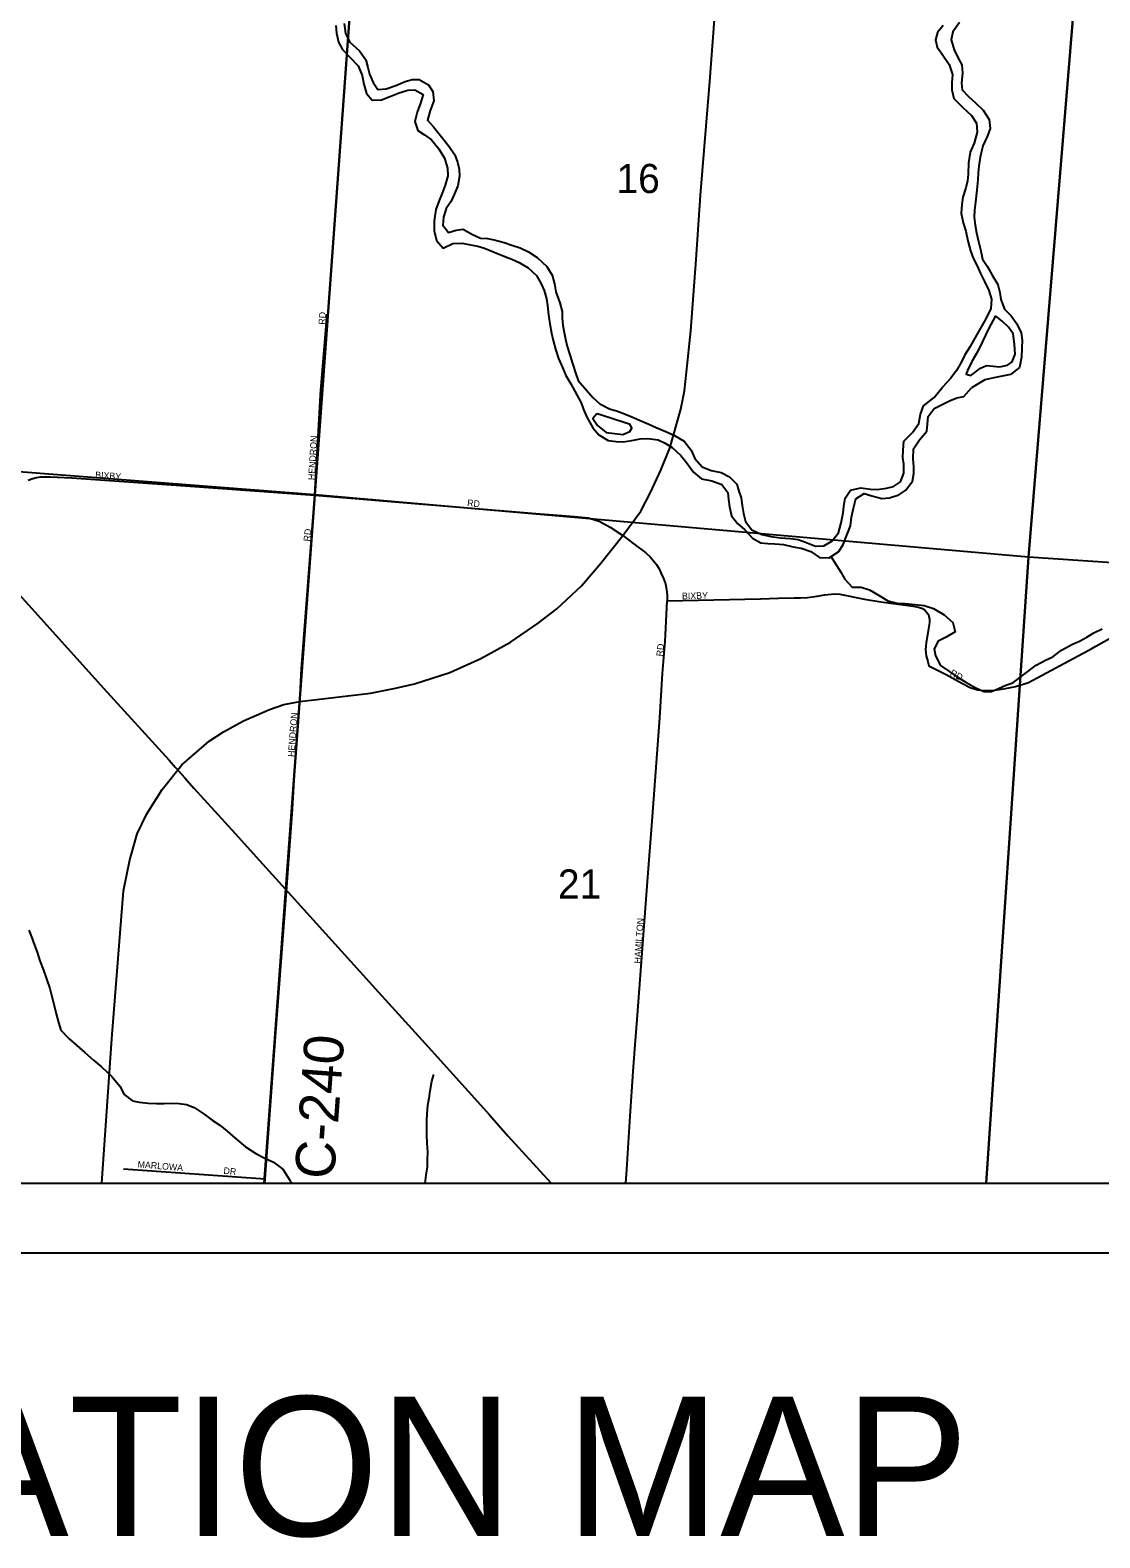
# Model space of a CAD drawing. Extents: x 0 to 34, y 0 to 22.
# Drawn here: x 5.595 to 7.131, y 13.591 to 15.756 of the extents above; entities that cross this region are included whole.
import ezdxf

# ---------------------------------------------------------------- set-up
doc = ezdxf.new("R2010")
doc.units = 0
for name, color, linetype in [('GM_X_City_Street', 7, 'Continuous'), ('GM_X_City_Street_Text', 7, 'Continuous'), ('GM_X_County_Road', 7, 'Continuous'), ('GM_X_County_Road_Text', 7, 'Continuous'), ('GM_X_Minor_River', 7, 'Continuous'), ('GM_X_Rail_Line', 7, 'Continuous'), ('GM_X_Section', 7, 'Continuous'), ('GM_X_Section_Text', 7, 'Continuous'), ('GM_X_State_Route', 7, 'Continuous'), ('GM_X_Township', 7, 'Continuous'), ('GM_X_Township_Road', 7, 'Continuous'), ('GM_X_Township_Subdivision', 7, 'Continuous'), ('GM_X_Township_Subdivision_Text', 7, 'Continuous'), ('SH_Data', 7, 'Continuous')]:
    doc.layers.add(name, color=color, linetype=linetype)

msp = doc.modelspace()

# ---------------------------------------------------------------- linework, layer by layer
at = {"layer": 'GM_X_City_Street'}
for points in [[(6.0119, 15.2328), (6.0214, 15.3483)], [(6.0039, 15.0882), (6.0118, 15.2315), (6.0119, 15.2328)], [(5.5921, 15.1097), (5.5987, 15.112), (5.604, 15.1135), (5.6097, 15.1143), (5.6158, 15.1146), (5.6238, 15.1146), (5.6549, 15.1131), (5.818, 15.1016), (6.0039, 15.0882), (6.3211, 15.062), (6.3526, 15.0594), (6.377, 15.0576), (6.3818, 15.0571)], [(5.9741, 14.6791), (5.9747, 14.6891), (5.9821, 14.7921), (5.9848, 14.8387), (6.0039, 15.0882)], [(6.3818, 15.0571), (6.3966, 15.0555), (6.4047, 15.0533), (6.4121, 15.0509), (6.4282, 15.0422), (6.4465, 15.03), (6.4626, 15.018), (6.4793, 15.0055), (6.486, 14.9992), (6.4904, 14.9938), (6.4947, 14.9884), (6.4983, 14.9825), (6.5011, 14.9765), (6.5049, 14.9683), (6.5075, 14.9606), (6.509, 14.9527), (6.5098, 14.9445), (6.5101, 14.9364)], [(7.1255, 14.8711), (7.154, 14.887), (7.1931, 14.9094), (7.2643, 14.9712), (7.2708, 14.9757), (7.2754, 14.9782), (7.2819, 14.9817), (7.2893, 14.9851), (7.2981, 14.9851)], [(6.5101, 14.9364), (6.6441, 14.9394), (6.6698, 14.9402), (6.6925, 14.9407), (6.6996, 14.9406)], [(6.6996, 14.9406), (6.7014, 14.9406), (6.7117, 14.941), (6.7254, 14.9431), (6.7365, 14.9452), (6.7454, 14.9461), (6.7524, 14.9463), (6.7578, 14.9459), (6.7936, 14.939), (6.8167, 14.9351), (6.8633, 14.929), (6.8684, 14.9279), (6.8723, 14.9269), (6.8767, 14.9253), (6.8804, 14.9227), (6.8831, 14.9198), (6.8852, 14.9168), (6.8859, 14.9142), (6.8867, 14.9102), (6.8867, 14.9055), (6.886, 14.8995), (6.8821, 14.876), (6.8811, 14.8664), (6.8818, 14.8576), (6.8842, 14.8495), (6.886, 14.8431), (6.9106, 14.8305), (6.9342, 14.8179), (6.9453, 14.8121), (6.9555, 14.8087), (6.9657, 14.8075), (6.9807, 14.8082), (6.9961, 14.8105), (7.0101, 14.8133), (7.0277, 14.8187), (7.0288, 14.8193)], [(6.4636, 14.2925), (6.4672, 14.3414), (6.4815, 14.5333), (6.4887, 14.6262), (6.4994, 14.7684), (6.5034, 14.8322), (6.5069, 14.8782), (6.5101, 14.9364)]]:
    msp.add_lwpolyline(points, dxfattribs=at)
at = {"layer": 'GM_X_County_Road'}
for points in [[(5.932, 14.1), (5.9324, 14.1065), (5.9477, 14.3172), (5.9632, 14.5192), (5.9717, 14.6374), (5.9741, 14.6791)], [(6.4505, 14.1), (6.4518, 14.12), (6.457, 14.1964), (6.4613, 14.2604), (6.4636, 14.2925)]]:
    msp.add_lwpolyline(points, dxfattribs=at)
at = {"layer": 'GM_X_Minor_River'}
for points in [[(6.0339, 15.7624), (6.0349, 15.7514), (6.0378, 15.7385), (6.0438, 15.7282), (6.0539, 15.7178), (6.0659, 15.7045), (6.0718, 15.6908), (6.0743, 15.6782), (6.078, 15.6649), (6.0862, 15.6553), (6.0995, 15.6556), (6.1128, 15.6612), (6.1249, 15.6657), (6.1375, 15.6697), (6.1473, 15.6704), (6.1594, 15.6635), (6.1555, 15.651), (6.1508, 15.6381), (6.1477, 15.6249), (6.1517, 15.6119), (6.1615, 15.6058), (6.1716, 15.5985), (6.1821, 15.5855), (6.1903, 15.5722), (6.1943, 15.5577), (6.195, 15.5467), (6.1911, 15.5331)], [(6.046, 15.7653), (6.0481, 15.7513), (6.0541, 15.7387), (6.068, 15.7261), (6.0773, 15.7131), (6.0802, 15.7021), (6.0824, 15.6926), (6.0876, 15.6808), (6.0943, 15.6705), (6.1064, 15.6715), (6.1201, 15.6763), (6.1338, 15.6823), (6.1437, 15.6852), (6.1539, 15.6848), (6.1671, 15.6775), (6.1734, 15.6679), (6.1748, 15.6542), (6.1694, 15.6403), (6.1658, 15.6266), (6.1741, 15.6171), (6.1857, 15.6026), (6.1969, 15.5888), (6.2051, 15.577), (6.2088, 15.5663), (6.211, 15.5561), (6.2116, 15.5462)], [(6.9062, 15.7625), (6.8982, 15.7523), (6.8954, 15.7421), (6.898, 15.7315), (6.9051, 15.7215), (6.9148, 15.7067), (6.9196, 15.6922), (6.9191, 15.6801), (6.919, 15.6702), (6.9215, 15.6577), (6.9346, 15.645), (6.947, 15.6332), (6.9541, 15.6225), (6.9551, 15.6092), (6.9508, 15.5937), (6.945, 15.5808), (6.9426, 15.5653), (6.9424, 15.5493), (6.9416, 15.5395), (6.9388, 15.5293), (6.9349, 15.516), (6.9333, 15.5054), (6.9324, 15.4929), (6.9353, 15.4792), (6.939, 15.4674), (6.9419, 15.4533), (6.9459, 15.4389), (6.9496, 15.4286), (6.9552, 15.4176), (6.96, 15.4065), (6.966, 15.3951), (6.9719, 15.3821), (6.9759, 15.3696), (6.9751, 15.3563), (6.9677, 15.3412), (6.96, 15.328), (6.9523, 15.3144), (6.9454, 15.3015), (6.9377, 15.2895), (6.9327, 15.2796), (6.9254, 15.2672), (6.9173, 15.2562), (6.9054, 15.243)], [(6.9301, 15.7669), (6.9201, 15.7537), (6.9181, 15.7419), (6.9222, 15.7275), (6.9281, 15.7157), (6.9333, 15.7061), (6.9344, 15.6947), (6.9327, 15.68), (6.9337, 15.6701), (6.9427, 15.6605), (6.9529, 15.6517), (6.9641, 15.641), (6.9727, 15.6276), (6.9737, 15.6147), (6.9702, 15.6041), (6.9636, 15.5898), (6.9597, 15.5735), (6.9577, 15.5606), (6.9565, 15.5511), (6.956, 15.5409), (6.9547, 15.5265), (6.9527, 15.509), (6.9514, 15.4973), (6.9509, 15.4874), (6.9523, 15.476), (6.9545, 15.465), (6.9574, 15.4525), (6.9603, 15.4392), (6.9629, 15.427), (6.9696, 15.4171), (6.977, 15.4041), (6.9848, 15.3908), (6.9878, 15.3794), (6.9892, 15.3691), (6.9944, 15.3554), (7.0041, 15.3455), (7.0123, 15.3344), (7.0186, 15.3211), (7.0201, 15.3108), (7.0192, 15.299), (7.0191, 15.2865), (7.0159, 15.2714), (7.0033, 15.2612), (6.9889, 15.2587), (6.979, 15.2565), (6.9661, 15.2536), (6.9473, 15.2421)], [(6.2116, 15.5462), (6.2092, 15.5325), (6.2038, 15.5197), (6.1992, 15.5095), (6.1927, 15.4997), (6.1887, 15.4872), (6.1879, 15.4758), (6.1961, 15.4651), (6.2071, 15.4688), (6.217, 15.4699), (6.2294, 15.4629), (6.2418, 15.4571), (6.2517, 15.4567), (6.2615, 15.4547), (6.2759, 15.4508), (6.2868, 15.4473), (6.2989, 15.4434), (6.3106, 15.4376), (6.323, 15.4295), (6.3369, 15.4165), (6.3447, 15.4039), (6.348, 15.3914), (6.3502, 15.38), (6.3557, 15.3644), (6.359, 15.3518), (6.3593, 15.3424), (6.3603, 15.3321), (6.3621, 15.3218), (6.3639, 15.3123), (6.3665, 15.3017), (6.3705, 15.288), (6.3742, 15.277), (6.3786, 15.2625), (6.3819, 15.253)], [(6.1911, 15.5331), (6.1868, 15.5217), (6.1825, 15.5115), (6.1779, 15.4983), (6.1751, 15.482), (6.1753, 15.4679), (6.1786, 15.4539), (6.1883, 15.4428), (6.202, 15.4495), (6.2153, 15.4498), (6.2277, 15.4474), (6.238, 15.4458), (6.2478, 15.4427), (6.2617, 15.4373), (6.2745, 15.4318), (6.287, 15.4272), (6.2976, 15.4222), (6.3104, 15.4148), (6.3224, 15.4037), (6.3291, 15.3916), (6.3335, 15.382), (6.3364, 15.3702), (6.3379, 15.3604), (6.3396, 15.3471), (6.3414, 15.3342), (6.3439, 15.3209), (6.3461, 15.3102), (6.3494, 15.2977), (6.3538, 15.2843), (6.3597, 15.2714), (6.3642, 15.26), (6.3716, 15.2478)], [(6.9818, 15.3456), (6.9714, 15.3268), (6.9629, 15.309), (6.9555, 15.2939), (6.9478, 15.2799), (6.9413, 15.2674), (6.9393, 15.2621), (6.9461, 15.2602), (6.9602, 15.2707), (6.9686, 15.2744), (6.9784, 15.2732), (6.9875, 15.2724), (6.9989, 15.2749), (7.0057, 15.2794), (7.0096, 15.2904), (7.009, 15.3048), (7.0069, 15.32), (7.0002, 15.3296), (6.9912, 15.338)], [(6.9912, 15.338), (6.9818, 15.3456)], [(6.3716, 15.2478), (6.3862, 15.2208), (6.3899, 15.2112), (6.3947, 15.2002), (6.4031, 15.1849), (6.4117, 15.1749), (6.4252, 15.1667), (6.4369, 15.1651), (6.4468, 15.1645), (6.4593, 15.1666), (6.4714, 15.1691), (6.4824, 15.1697), (6.4971, 15.1676), (6.5069, 15.1629), (6.517, 15.1564), (6.5297, 15.1452), (6.5376, 15.1352), (6.5476, 15.1214), (6.5595, 15.1114), (6.5739, 15.1085), (6.5886, 15.1034), (6.5971, 15.0919), (6.5981, 15.082), (6.5995, 15.0714), (6.6023, 15.0584), (6.6112, 15.0477), (6.6217, 15.0384), (6.6325, 15.0265), (6.6445, 15.0199), (6.6547, 15.0186), (6.6646, 15.0181), (6.677, 15.0172), (6.691, 15.014), (6.7023, 15.0119), (6.7163, 15.0072), (6.729, 14.9986), (6.7426, 14.9981), (6.7564, 15.0074), (6.763, 15.0175), (6.7689, 15.0333), (6.7732, 15.0439), (6.7749, 15.0568), (6.7777, 15.0696), (6.7809, 15.0829), (6.7927, 15.0907), (6.804, 15.0871), (6.8184, 15.0835), (6.8294, 15.0845), (6.8427, 15.0888), (6.853, 15.0951), (6.8622, 15.1083), (6.8643, 15.1193), (6.8644, 15.1287), (6.8635, 15.1405), (6.864, 15.1545), (6.8722, 15.1677), (6.8829, 15.1801), (6.8838, 15.1903), (6.8851, 15.2009), (6.8936, 15.2125), (6.905, 15.2184), (6.9157, 15.2236), (6.926, 15.228), (6.9359, 15.2298), (6.9473, 15.2421)], [(6.3819, 15.253), (6.4034, 15.2285), (6.4131, 15.2193), (6.427, 15.2122), (6.4387, 15.209), (6.4485, 15.2051), (6.459, 15.2008), (6.4737, 15.1945), (6.4835, 15.1902), (6.494, 15.1855), (6.509, 15.1792), (6.5203, 15.1738), (6.5346, 15.1656), (6.5442, 15.1529), (6.5497, 15.1407), (6.5602, 15.1288), (6.5733, 15.1237), (6.5873, 15.1205), (6.5993, 15.1146), (6.6098, 15.1038), (6.613, 15.0939), (6.6163, 15.0844), (6.6177, 15.0734), (6.6194, 15.062), (6.6226, 15.0502), (6.6316, 15.0383), (6.6458, 15.0317), (6.659, 15.0288), (6.6726, 15.0271), (6.687, 15.0261), (6.6983, 15.0245), (6.7085, 15.0209), (6.7228, 15.015), (6.7349, 15.0152), (6.7467, 15.0219), (6.756, 15.0339), (6.76, 15.0483), (6.7628, 15.0626), (6.7637, 15.0721), (6.7658, 15.0838), (6.7731, 15.0955), (6.7883, 15.0987), (6.8019, 15.097), (6.8117, 15.0965), (6.825, 15.0982), (6.8353, 15.1007), (6.8452, 15.1074), (6.8499, 15.1198), (6.8497, 15.1327), (6.8487, 15.1422), (6.8489, 15.1529), (6.8498, 15.1657), (6.8625, 15.1781), (6.8714, 15.1912), (6.8738, 15.2045), (6.8781, 15.2162), (6.8935, 15.2285), (6.9054, 15.243)], [(6.4144, 15.2033), (6.4087, 15.2049), (6.4033, 15.1981), (6.41, 15.1882), (6.4224, 15.1782), (6.4462, 15.1755), (6.4561, 15.1796), (6.4592, 15.1845), (6.4566, 15.1894), (6.4509, 15.1914)], [(6.4509, 15.1914), (6.4144, 15.2033)], [(6.7453, 14.9998), (6.7596, 14.9774), (6.7653, 14.9675), (6.7755, 14.9561), (6.7887, 14.9561), (6.8008, 14.9523), (6.8144, 14.9439), (6.8269, 14.9363), (6.8405, 14.9333), (6.8519, 14.9325), (6.8655, 14.931), (6.8791, 14.9298), (6.8923, 14.9252), (6.9078, 14.9161), (6.9203, 14.9051), (6.9237, 14.8918), (6.9108, 14.8842), (6.8994, 14.8786), (6.8937, 14.8676), (6.8956, 14.8574), (6.9027, 14.8437), (6.9159, 14.8346), (6.9258, 14.8277), (6.939, 14.8197), (6.9522, 14.8121), (6.9647, 14.8064), (6.9757, 14.8064), (6.9859, 14.8106), (6.9965, 14.8151), (7.0067, 14.8189), (7.0401, 14.8442)], [(7.0401, 14.8442), (7.0533, 14.851), (7.064, 14.8559), (7.0765, 14.8654), (7.092, 14.8744), (7.1022, 14.8786), (7.1128, 14.8842), (7.1227, 14.8903), (7.1348, 14.8963)], [(5.593, 14.4635), (5.5967, 14.4539), (5.601, 14.4421), (5.605, 14.4318), (5.609, 14.4196), (5.614, 14.4062), (5.6184, 14.3936), (5.623, 14.3799), (5.6255, 14.3704), (5.6298, 14.3532), (5.6323, 14.3433), (5.6358, 14.3307), (5.6391, 14.3197), (5.651, 14.3077), (5.6622, 14.2977), (5.6733, 14.288), (5.686, 14.2768), (5.6972, 14.2675), (5.7125, 14.2532), (5.7236, 14.2397), (5.7299, 14.2275), (5.7418, 14.2186), (5.7516, 14.2165), (5.7645, 14.2151), (5.7762, 14.2146), (5.7875, 14.2144), (5.7974, 14.215), (5.8091, 14.2148), (5.8197, 14.2134), (5.8306, 14.2087), (5.8448, 14.1994), (5.8564, 14.1908), (5.8673, 14.1834), (5.8781, 14.1749), (5.8896, 14.1649), (5.9042, 14.1525), (5.9192, 14.1427), (5.9301, 14.1369), (5.9443, 14.1302), (5.9578, 14.1201)], [(6.1623, 14.1), (6.1639, 14.1117), (6.1656, 14.1238), (6.1658, 14.1344), (6.166, 14.1446), (6.1651, 14.1579), (6.1649, 14.1686), (6.1647, 14.1784), (6.1649, 14.1902), (6.1654, 14.1997), (6.1664, 14.2122), (6.1681, 14.2224), (6.1694, 14.233), (6.1719, 14.2466), (6.1747, 14.2564)], [(5.9578, 14.1201), (5.9681, 14.1047), (5.9707, 14.1)]]:
    msp.add_lwpolyline(points, dxfattribs=at)
at = {"layer": 'GM_X_Rail_Line'}
msp.add_lwpolyline([(5.383, 15.1619), (5.6015, 14.9204), (5.7005, 14.8112), (5.7944, 14.7075), (5.8037, 14.697), (5.817, 14.6821), (5.8302, 14.6673), (5.8892, 14.6024), (5.9242, 14.5634), (5.9656, 14.5181), (6.0952, 14.3747), (6.167, 14.2955), (6.2546, 14.1982), (6.2812, 14.1683), (6.3374, 14.1064), (6.3434, 14.1)], dxfattribs=at)
at = {"layer": 'GM_X_Section'}
for p, q in [((5.4703, 14.1), (5.9313, 14.1)), ((5.9313, 14.1), (6.9683, 14.1)), ((6.9683, 14.1), (7.9848, 14.1))]:
    msp.add_line(p, q, dxfattribs=at)
for points in [[(5.0408, 16.1927), (6.0779, 16.1089), (6.0038, 15.0886), (4.9746, 15.1686)], [(6.0779, 16.1089), (7.1133, 16.022), (7.0289, 14.9993), (6.0038, 15.0886)], [(7.1133, 16.022), (8.1366, 15.948), (8.0511, 14.9304), (7.0289, 14.9993)]]:
    msp.add_lwpolyline(points, close=True, dxfattribs=at)
for points in [[(5.9313, 14.1), (6.0038, 15.0886), (4.9746, 15.1686), (4.9053, 14.1412), (5.4703, 14.1)], [(6.9683, 14.1), (7.0289, 14.9993), (6.0038, 15.0886), (5.9313, 14.1)], [(7.9848, 14.1), (8.0511, 14.9304), (7.0289, 14.9993), (6.9683, 14.1)]]:
    msp.add_lwpolyline(points, dxfattribs=at)
at = {"layer": 'GM_X_State_Route'}
for points in [[(5.7408, 14.5746), (5.7488, 14.6018), (5.7625, 14.6307), (5.7845, 14.6657), (5.8126, 14.7007), (5.852, 14.7347), (5.8725, 14.7482), (5.9016, 14.7643), (5.9386, 14.7805), (5.9595, 14.7875), (5.9821, 14.7921), (6.084, 14.804), (6.1197, 14.8109), (6.1471, 14.817), (6.198, 14.8337), (6.2421, 14.8535), (6.2847, 14.877), (6.3245, 14.9044), (6.3514, 14.925), (6.3867, 14.9578), (6.4146, 14.9907), (6.4465, 15.03), (6.472, 15.0652), (6.4862, 15.0921), (6.5009, 15.124), (6.5136, 15.1558), (6.5295, 15.2118), (6.535, 15.2379), (6.5376, 15.2646), (6.5438, 15.3243), (6.5518, 15.4266), (6.558, 15.5191), (6.5714, 15.682), (6.5813, 15.816)], [(5.6981, 14.1), (5.7125, 14.3077), (5.7289, 14.5202), (5.7379, 14.5646), (5.7408, 14.5746)]]:
    msp.add_lwpolyline(points, dxfattribs=at)
at = {"layer": 'GM_X_Township'}
msp.add_lwpolyline([(3.9541, 14.1), (9.4, 14.1), (9.4, 17.8295)], dxfattribs=at)
at = {"layer": 'GM_X_Township_Road'}
msp.add_lwpolyline([(7.0288, 14.8193), (7.1199, 14.868), (7.1255, 14.8711)], dxfattribs=at)
at = {"layer": 'GM_X_Township_Subdivision'}
msp.add_lwpolyline([(5.7292, 14.1207), (5.9324, 14.1065)], dxfattribs=at)
at = {"layer": 'SH_Data'}
for p, q in [((2.6, 14.1), (9.4, 14.1)), ((2.5, 14), (9.5, 14))]:
    msp.add_line(p, q, dxfattribs=at)

# ---------------------------------------------------------------- texts
at = {"layer": 'GM_X_City_Street_Text'}
for s, rotation, p in [('RD', 86.9884, (6.0187, 15.3328)), ('HENDRON', 86.6322, (6.0037, 15.1095)), ('BIXBY', 356.0116, (5.6881, 15.1127)), ('RD', 353.9934, (6.2223, 15.0727)), ('RD', 83.9946, (5.997, 15.0213)), ('BIXBY', 1.3315, (6.5313, 14.9386)), ('RD', 83.9946, (6.5037, 14.8563)), ('RD', 332.0986, (6.9154, 14.83)), ('HENDRON', 85.7938, (5.9745, 14.712)), ('HAMILTON', 86.1338, (6.472, 14.4154))]:
    msp.add_text(s, height=0.00947, rotation=rotation, dxfattribs=at).set_placement(p)
at = {"layer": 'GM_X_County_Road_Text'}
msp.add_text('C-240', height=0.05682, rotation=85.8754, dxfattribs=at).set_placement((6.0314, 14.1048))
at = {"layer": 'GM_X_Section_Text'}
for s, p in [('16', (6.4371, 15.522)), ('21', (6.353, 14.5089))]:
    msp.add_text(s, height=0.04186, rotation=0, dxfattribs=at).set_placement(p)
at = {"layer": 'GM_X_Township_Subdivision_Text'}
for s, rotation, p in [('MARLOWA', 355.3008, (5.749, 14.1229)), ('DR', 353.9832, (5.8723, 14.1137))]:
    msp.add_text(s, height=0.00947, rotation=rotation, dxfattribs=at).set_placement(p)
at = {"layer": 'SH_Data'}
msp.add_text('LOCATION MAP', height=0.2, dxfattribs=at).set_placement((4.9221, 13.5938))

doc.saveas('drawing.dxf')
